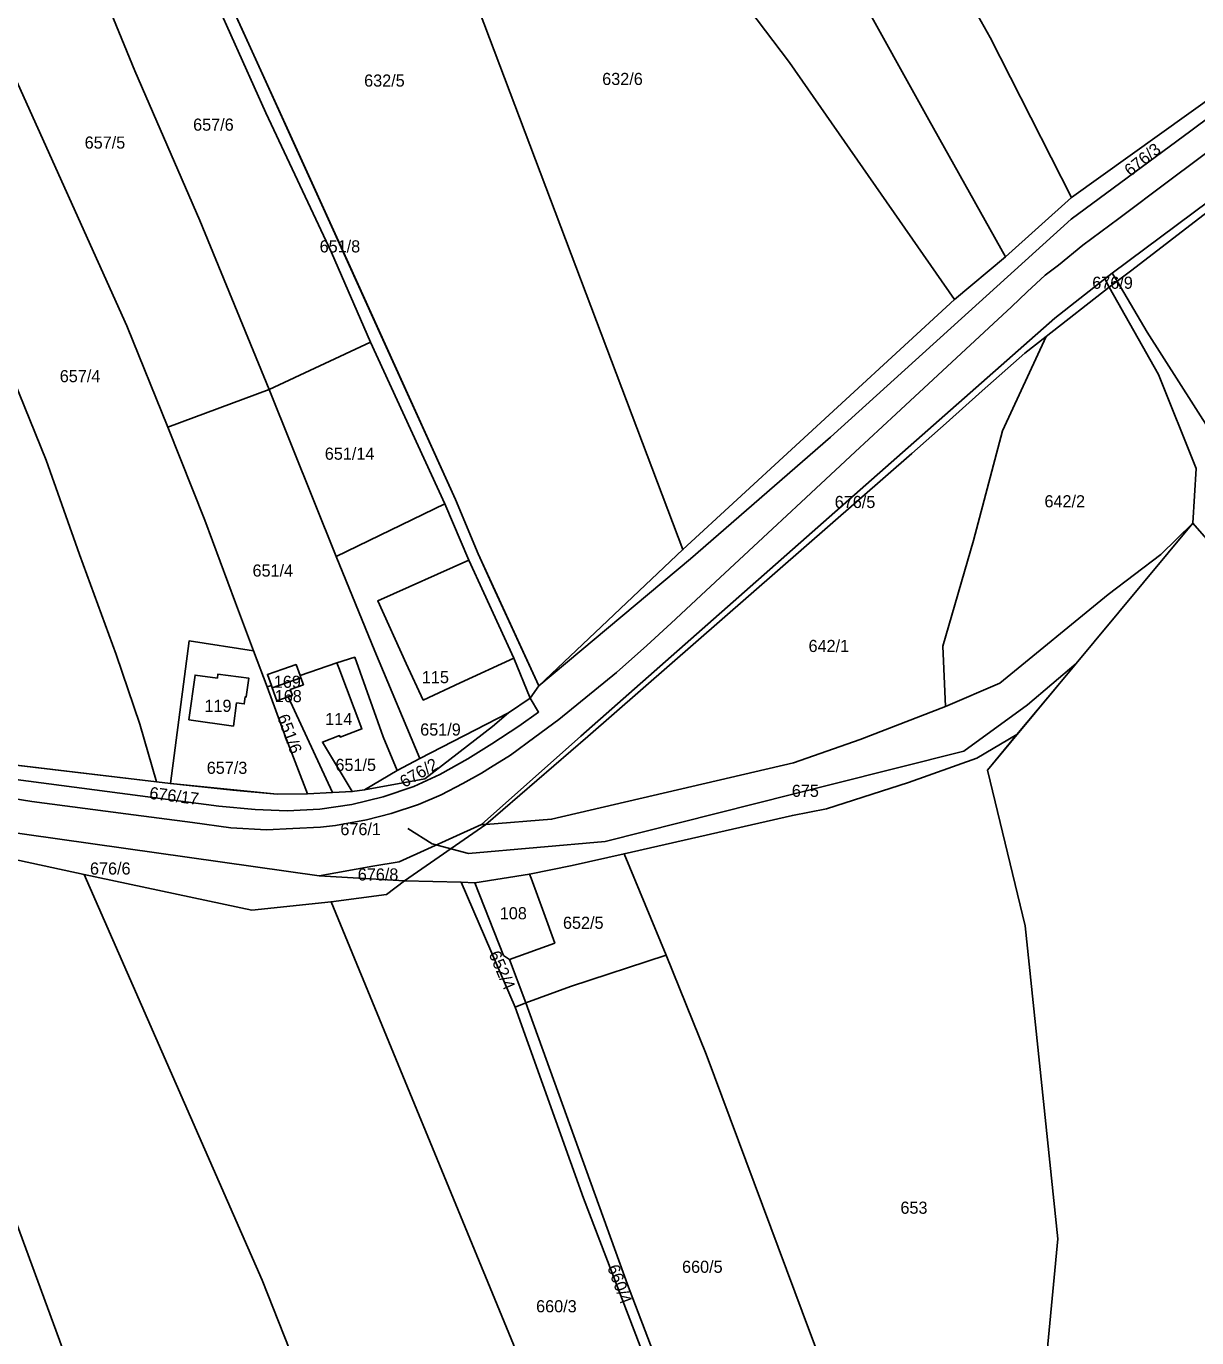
# Model space of a CAD drawing. Extents: x -629983 to -626385, y -1072828 to -1067897.
# Drawn here: x -627472.6 to -627182.9, y -1070989.8 to -1070665.2 of the extents above; entities that cross this region are included whole.
import ezdxf

# ---------------------------------------------------------------- set-up
doc = ezdxf.new("R2010")
doc.units = 0
for name, color, linetype in [('Cesty', 7, 'Continuous'), ('Parcela nároku', 7, 'Continuous'), ('Parcelní číslo', 7, 'Continuous'), ('Plocha PÚ', 7, 'Continuous'), ('Převzatý obvod_Vraclav', 7, 'Continuous'), ('Silnice ŘSD', 7, 'Continuous'), ('Vnitřní obvod_šetřený', 7, 'Continuous')]:
    doc.layers.add(name, color=color, linetype=linetype)

msp = doc.modelspace()

# ---------------------------------------------------------------- linework, layer by layer
at = {"layer": 'Cesty'}
msp.add_lwpolyline([(-627212.76, -1070822.88), (-627224.8, -1070833.14), (-627240.53, -1070844.57), (-627273.7, -1070852.92), (-627329.35, -1070866.93), (-627363.11, -1070869.9), (-627372.12, -1070867.54), (-627378.18, -1070863.7)], dxfattribs=at)
at = {"layer": 'Parcela nároku'}
for points in [[(-627345.75, -1070479.75), (-627344.14, -1070479.15), (-627339.84, -1070477.13), (-627333.5, -1070479.48), (-627296.66, -1070498.52), (-627275.1, -1070508.7), (-627258, -1070516.22), (-627228.28, -1070532.83), (-627198.25, -1070547.66), (-627164.03, -1070550.6), (-627101.84, -1070557.31), (-627079.28, -1070557.75), (-627047.73, -1070561.25), (-627009.17, -1070562.89), (-627133.47, -1070649.92), (-627213.86, -1070707.57), (-627234.07, -1070668.02), (-627251.08, -1070637.59), (-627269.7, -1070609.62), (-627295.58, -1070573.7), (-627307.19, -1070559.96), (-627314.16, -1070551.29), (-627330.36, -1070531.39), (-627360.17, -1070494.95)], [(-627314.16, -1070551.29), (-627330.36, -1070531.39), (-627360.17, -1070494.95), (-627373.54, -1070509.05), (-627353.57, -1070535.93), (-627302.15, -1070602.21), (-627283, -1070629.7), (-627267.06, -1070656.21), (-627249.24, -1070688.39), (-627230.23, -1070722.24), (-627213.86, -1070707.57), (-627234.07, -1070668.02), (-627251.08, -1070637.59), (-627269.7, -1070609.62), (-627295.58, -1070573.7), (-627307.19, -1070559.96)], [(-627267.06, -1070656.21), (-627249.24, -1070688.39), (-627230.23, -1070722.24), (-627242.86, -1070732.84), (-627283.73, -1070674.15), (-627293.78, -1070660.89), (-627306.22, -1070642.08), (-627338.73, -1070596.09), (-627370.14, -1070560.09), (-627392.8, -1070532.82), (-627373.54, -1070509.05), (-627353.57, -1070535.93), (-627302.15, -1070602.21), (-627283, -1070629.7)], [(-627345.73, -1070828.4), (-627310.09, -1070794.7), (-627242.86, -1070732.84), (-627230.23, -1070722.24), (-627213.86, -1070707.57), (-627133.47, -1070649.92), (-627009.17, -1070562.89), (-626993.73, -1070553.31), (-626992.54, -1070553.28), (-627154.49, -1070668.8), (-627184.39, -1070691.07), (-627213.95, -1070712.95), (-627273.55, -1070766.93), (-627308.24, -1070796.99)], [(-627398.36, -1070567.15), (-627370.14, -1070560.09), (-627338.73, -1070596.09), (-627306.22, -1070642.08), (-627293.78, -1070660.89), (-627283.73, -1070674.15), (-627242.86, -1070732.84), (-627310.09, -1070794.7), (-627360.53, -1070661.36)], [(-627360.53, -1070661.36), (-627310.09, -1070794.7), (-627345.73, -1070828.4), (-627360.76, -1070795.75), (-627366.36, -1070782.3), (-627384.74, -1070741.85), (-627400.99, -1070705.92), (-627417.12, -1070670.56), (-627430.56, -1070640.91), (-627435.89, -1070628.45), (-627445.75, -1070607.53), (-627463.29, -1070576.43), (-627398.36, -1070567.15)], [(-627413.29, -1070686.67), (-627433.51, -1070641.56), (-627449.08, -1070608.65), (-627469.47, -1070618.25), (-627445.72, -1070676.24), (-627429.68, -1070713.29), (-627412.5, -1070755.1), (-627387.43, -1070743.37), (-627397.03, -1070721.21)], [(-627430.56, -1070640.91), (-627435.89, -1070628.45), (-627445.75, -1070607.53), (-627449.08, -1070608.65), (-627433.51, -1070641.56), (-627413.29, -1070686.67), (-627397.03, -1070721.21), (-627387.43, -1070743.37), (-627368.97, -1070783.41), (-627363.03, -1070797.32), (-627351.95, -1070821.55), (-627347.85, -1070831.5), (-627345.73, -1070828.4), (-627360.76, -1070795.75), (-627366.36, -1070782.3), (-627384.74, -1070741.85), (-627400.99, -1070705.92), (-627417.12, -1070670.56)], [(-627445.72, -1070676.24), (-627429.68, -1070713.29), (-627412.5, -1070755.1), (-627437.6, -1070764.46), (-627447.75, -1070739.38), (-627476.84, -1070674.65), (-627497.28, -1070630.97), (-627469.47, -1070618.25)], [(-627428.4, -1070787.43), (-627420.85, -1070807.85), (-627416.32, -1070819.79), (-627432.25, -1070817.28), (-627436.93, -1070852.6), (-627440.33, -1070852.16), (-627444.51, -1070837.95), (-627450.33, -1070820.66), (-627459.42, -1070795.95), (-627467.69, -1070772.62), (-627485.16, -1070729.61), (-627494.54, -1070708.53), (-627524.44, -1070643.36), (-627497.28, -1070630.97), (-627476.84, -1070674.65), (-627447.75, -1070739.38), (-627437.6, -1070764.46)], [(-627135.92, -1070675.75), (-627203.84, -1070726.3), (-627202.58, -1070728.32), (-627198.97, -1070725.59), (-627161.65, -1070696.9), (-627086.98, -1070641.42), (-627087.58, -1070639.08)], [(-627526.57, -1070644.43), (-627524.44, -1070643.36), (-627494.54, -1070708.53), (-627485.16, -1070729.61), (-627467.69, -1070772.62), (-627459.42, -1070795.95), (-627450.33, -1070820.66), (-627444.51, -1070837.95), (-627440.33, -1070852.16), (-627482.19, -1070847.21), (-627487.27, -1070833.79), (-627496.33, -1070806.96), (-627518.25, -1070750.64), (-627541.19, -1070696.77), (-627538.48, -1070690.73)], [(-627359.96, -1070862.72), (-627335.31, -1070840.92), (-627218.06, -1070737.43), (-627205.69, -1070727.72), (-627204.61, -1070729.74), (-627220.17, -1070742.01), (-627225.42, -1070746.14), (-627236.01, -1070755.45), (-627244.91, -1070763.47), (-627253.44, -1070770.95), (-627333.6, -1070840.96), (-627358.84, -1070862.72)], [(-627205.69, -1070727.72), (-627203.84, -1070726.3), (-627202.58, -1070728.32), (-627204.61, -1070729.74)], [(-627124.68, -1070815.56), (-627100.86, -1070825.79), (-627112.72, -1070834.32), (-627114.07, -1070833.53), (-627155.58, -1070814.85), (-627170.74, -1070803.18), (-627183.85, -1070788.14), (-627183.07, -1070774.61), (-627192.4, -1070751.35), (-627204.61, -1070729.74), (-627202.58, -1070728.32), (-627195.15, -1070740.89), (-627179.46, -1070765.48), (-627171.13, -1070779.58), (-627160.79, -1070795.62), (-627147.68, -1070806.17)], [(-627220.17, -1070742.01), (-627204.61, -1070729.74), (-627192.4, -1070751.35), (-627183.07, -1070774.61), (-627183.85, -1070788.14), (-627191.81, -1070795.9), (-627204.83, -1070805.81), (-627231.68, -1070827.78), (-627245.05, -1070833.52), (-627245.75, -1070818.59), (-627238.15, -1070792.48), (-627231.02, -1070765.37)], [(-627387.43, -1070743.37), (-627368.97, -1070783.41), (-627395.86, -1070796.42), (-627412.5, -1070755.1)], [(-627220.17, -1070742.01), (-627231.02, -1070765.37), (-627238.15, -1070792.48), (-627245.75, -1070818.59), (-627245.05, -1070833.52), (-627266.24, -1070841.69), (-627282.74, -1070847.49), (-627342.58, -1070861.45), (-627358.84, -1070862.72), (-627333.6, -1070840.96), (-627253.44, -1070770.95), (-627244.91, -1070763.47), (-627236.01, -1070755.45), (-627225.42, -1070746.14)], [(-627411.94, -1070828.31), (-627412.92, -1070825.6), (-627409.06, -1070824.28), (-627405.8, -1070823.17), (-627404.82, -1070825.87), (-627395.71, -1070822.75), (-627391.28, -1070821.34), (-627384.3, -1070841.06), (-627380.78, -1070849.34), (-627375.19, -1070846.37), (-627386.3, -1070819.87), (-627395.86, -1070796.42), (-627412.5, -1070755.1), (-627437.6, -1070764.46), (-627428.4, -1070787.43), (-627420.85, -1070807.85), (-627416.32, -1070819.79), (-627412.96, -1070828.66)], [(-627378.56, -1070822.89), (-627385.61, -1070807.42), (-627363.03, -1070797.32), (-627368.97, -1070783.41), (-627395.86, -1070796.42), (-627386.3, -1070819.87), (-627375.19, -1070846.37), (-627353.23, -1070835.08), (-627347.85, -1070831.5), (-627351.95, -1070821.55), (-627365.18, -1070827.7), (-627374.34, -1070831.96)], [(-627217.22, -1070828.24), (-627208.31, -1070817.53), (-627183.85, -1070788.14), (-627191.81, -1070795.9), (-627204.83, -1070805.81), (-627231.68, -1070827.78), (-627245.05, -1070833.52), (-627266.24, -1070841.69), (-627282.74, -1070847.49), (-627342.58, -1070861.45), (-627358.84, -1070862.72), (-627378.98, -1070876.68), (-627364.95, -1070877.04), (-627361.61, -1070877.18), (-627348.05, -1070875.02), (-627337.52, -1070872.91), (-627324.65, -1070869.98), (-627282.97, -1070860.49), (-627274.55, -1070858.83), (-627254.24, -1070852.32), (-627237.3, -1070846.31), (-627227.43, -1070840.51)], [(-627363.03, -1070797.32), (-627351.95, -1070821.55), (-627365.18, -1070827.7), (-627374.34, -1070831.96), (-627378.56, -1070822.89), (-627385.61, -1070807.42)], [(-627408.71, -1070840.35), (-627402.98, -1070855.15), (-627410.49, -1070855.25), (-627421.44, -1070854.21), (-627436.93, -1070852.6), (-627432.25, -1070817.28), (-627416.32, -1070819.79), (-627412.96, -1070828.66)], [(-627395.23, -1070823.98), (-627389.52, -1070839.07), (-627394.9, -1070841.11), (-627395.06, -1070840.76), (-627399.32, -1070842.35), (-627391.9, -1070854.61), (-627396.81, -1070854.85), (-627407.8, -1070831.18), (-627406.72, -1070830.81), (-627407.26, -1070829.3), (-627403.99, -1070828.15), (-627404.62, -1070826.41), (-627404.82, -1070825.87), (-627395.71, -1070822.75)], [(-627384.3, -1070841.06), (-627391.28, -1070821.34), (-627395.71, -1070822.75), (-627395.23, -1070823.98), (-627389.52, -1070839.07), (-627394.9, -1070841.11), (-627395.06, -1070840.76), (-627399.32, -1070842.35), (-627391.9, -1070854.61), (-627388.87, -1070854.16), (-627380.78, -1070849.34)], [(-627425.15, -1070825.51), (-627425.28, -1070826.52), (-627430.81, -1070825.75), (-627432.34, -1070836.81), (-627421.34, -1070838.38), (-627420.55, -1070832.65), (-627418.64, -1070832.91), (-627418.4, -1070831.15), (-627418.14, -1070831.19), (-627417.51, -1070826.57)], [(-627420.55, -1070832.65), (-627418.64, -1070832.91), (-627418.4, -1070831.15), (-627418.14, -1070831.19), (-627417.51, -1070826.57), (-627425.15, -1070825.51), (-627425.28, -1070826.52), (-627430.81, -1070825.75), (-627432.34, -1070836.81), (-627421.34, -1070838.38)], [(-627412.92, -1070825.6), (-627409.06, -1070824.28), (-627405.8, -1070823.17), (-627404.82, -1070825.87), (-627404.62, -1070826.41), (-627411.72, -1070828.91), (-627411.94, -1070828.31)], [(-627410.55, -1070832.11), (-627411.72, -1070828.91), (-627411.94, -1070828.31), (-627412.96, -1070828.66), (-627408.71, -1070840.35), (-627402.98, -1070855.15), (-627396.81, -1070854.85), (-627407.8, -1070831.18)], [(-627407.26, -1070829.3), (-627406.72, -1070830.81), (-627407.8, -1070831.18), (-627410.55, -1070832.11), (-627411.72, -1070828.91), (-627404.62, -1070826.41), (-627403.99, -1070828.15)], [(-627388.87, -1070854.16), (-627380.78, -1070849.34), (-627375.19, -1070846.37), (-627353.23, -1070835.08), (-627357.2, -1070838.49), (-627373.98, -1070851.44)], [(-627324.65, -1070869.98), (-627282.97, -1070860.49), (-627274.55, -1070858.83), (-627254.24, -1070852.32), (-627237.3, -1070846.31), (-627227.43, -1070840.51), (-627234.72, -1070849.27), (-627225.38, -1070887.83), (-627217.27, -1070965.31), (-627222.05, -1071015.66), (-627216.92, -1071077.12), (-627218.51, -1071078), (-627242.92, -1071082.98), (-627278.49, -1070988.8), (-627304.36, -1070919.55), (-627314.21, -1070895.06)], [(-627425.39, -1071101.61), (-627464.39, -1070990.31), (-627494.83, -1070907.68), (-627511.34, -1070863.62), (-627558.97, -1070852.76), (-627563.32, -1070867.25), (-627565.13, -1070881.01), (-627553.22, -1070912.19), (-627487.28, -1071091.1), (-627484.82, -1071098.49), (-627477.62, -1071120.08), (-627464.68, -1071117.19), (-627425.29, -1071264.47), (-627411.23, -1071265.41), (-627404.64, -1071260.81), (-627372.04, -1071256.74)], [(-627400.11, -1070875.43), (-627378.98, -1070876.68), (-627383.46, -1070880.08), (-627397.15, -1070881.84), (-627416.76, -1070883.94), (-627458.27, -1070875.13), (-627511.34, -1070863.62), (-627512.8, -1070859.53)], [(-627511.34, -1070863.62), (-627458.27, -1070875.13), (-627414.24, -1070975.53), (-627351.5, -1071134.14), (-627344.19, -1071153.05), (-627310.58, -1071241.74), (-627330.46, -1071244.09), (-627344.95, -1071240.94), (-627370.43, -1071256.59), (-627372.04, -1071256.74), (-627425.39, -1071101.61), (-627464.39, -1070990.31), (-627494.83, -1070907.68)], [(-627386.84, -1070873.07), (-627380.27, -1070871.95), (-627359.96, -1070862.72), (-627358.84, -1070862.72), (-627378.98, -1070876.68), (-627400.11, -1070875.43)], [(-627314.21, -1070895.06), (-627324.65, -1070869.98), (-627337.52, -1070872.91), (-627348.05, -1070875.02), (-627347.65, -1070876.03), (-627344.53, -1070884.58), (-627341.79, -1070892.1), (-627353, -1070896.16), (-627348.99, -1070906.83), (-627337.88, -1070902.81)], [(-627243.27, -1071225.13), (-627253.31, -1071197.18), (-627293.78, -1071090.43), (-627315.1, -1071093.36), (-627352.03, -1070991.41), (-627397.15, -1070881.84), (-627416.76, -1070883.94), (-627458.27, -1070875.13), (-627414.24, -1070975.53), (-627351.5, -1071134.14), (-627344.19, -1071153.05), (-627310.58, -1071241.74), (-627279.45, -1071238.38), (-627256.78, -1071225.7)], [(-627334.65, -1070955.19), (-627351.59, -1070907.93), (-627364.95, -1070877.04), (-627378.98, -1070876.68), (-627383.46, -1070880.08), (-627397.15, -1070881.84), (-627352.03, -1070991.41), (-627315.1, -1071093.36), (-627293.78, -1071090.43), (-627283.43, -1071089)], [(-627364.95, -1070877.04), (-627361.61, -1070877.18), (-627354.49, -1070895.13), (-627353, -1070896.16), (-627348.99, -1070906.83), (-627351.59, -1070907.93)], [(-627344.53, -1070884.58), (-627347.65, -1070876.03), (-627348.05, -1070875.02), (-627361.61, -1070877.18), (-627354.49, -1070895.13), (-627353, -1070896.16), (-627341.79, -1070892.1)], [(-627314.21, -1070895.06), (-627304.36, -1070919.55), (-627278.49, -1070988.8), (-627242.92, -1071082.98), (-627249.56, -1071084.34), (-627281.03, -1071088.67), (-627323.76, -1070976.6), (-627348.99, -1070906.83), (-627337.88, -1070902.81)], [(-627348.99, -1070906.83), (-627323.76, -1070976.6), (-627281.03, -1071088.67), (-627283.43, -1071089), (-627334.65, -1070955.19), (-627351.59, -1070907.93)]]:
    msp.add_lwpolyline(points, close=True, dxfattribs=at)
for points in [[(-627483.4, -1070850.5), (-627424.93, -1070858.24), (-627415.96, -1070859.06), (-627407.99, -1070859.33), (-627399.98, -1070858.97), (-627392.06, -1070857.81), (-627384.28, -1070855.87), (-627376.68, -1070853.37), (-627370.28, -1070850.4), (-627363.31, -1070846.47), (-627357.37, -1070842.79), (-627350.7, -1070838.37), (-627345.8, -1070834.94), (-627347.85, -1070831.5), (-627345.73, -1070828.4), (-627308.24, -1070796.99), (-627273.55, -1070766.93), (-627213.95, -1070712.95), (-627184.39, -1070691.07), (-627154.49, -1070668.8), (-626992.54, -1070553.28)], [(-627087.58, -1070639.08), (-627135.92, -1070675.75), (-627203.84, -1070726.3), (-627205.69, -1070727.72), (-627218.06, -1070737.43), (-627335.31, -1070840.92), (-627359.96, -1070862.72), (-627380.27, -1070871.95), (-627386.84, -1070873.07), (-627400.11, -1070875.43), (-627512.8, -1070859.53)], [(-627161.65, -1070696.9), (-627198.97, -1070725.59), (-627202.58, -1070728.32), (-627195.15, -1070740.89), (-627179.46, -1070765.48)], [(-627482.19, -1070847.21), (-627440.33, -1070852.16), (-627436.93, -1070852.6), (-627421.44, -1070854.21), (-627410.49, -1070855.25), (-627402.98, -1070855.15), (-627396.81, -1070854.85), (-627391.9, -1070854.61), (-627388.87, -1070854.16), (-627373.98, -1070851.44), (-627357.2, -1070838.49), (-627353.23, -1070835.08), (-627347.85, -1070831.5), (-627345.8, -1070834.94), (-627350.7, -1070838.37), (-627357.37, -1070842.79), (-627363.31, -1070846.47), (-627370.28, -1070850.4), (-627376.68, -1070853.37), (-627384.28, -1070855.87), (-627392.06, -1070857.81), (-627399.98, -1070858.97), (-627407.99, -1070859.33), (-627415.96, -1070859.06), (-627424.93, -1070858.24), (-627483.4, -1070850.5)]]:
    msp.add_lwpolyline(points, dxfattribs=at)
at = {"layer": 'Plocha PÚ'}
for points in [[(-627430.56, -1070640.91), (-627417.12, -1070670.56), (-627407.65, -1070691.38), (-627392.86, -1070723.88), (-627366.36, -1070782.3), (-627360.76, -1070795.75), (-627357, -1070803.92), (-627345.73, -1070828.4), (-627347.85, -1070831.5), (-627353.23, -1070835.08), (-627375.19, -1070846.37), (-627380.78, -1070849.34), (-627388.87, -1070854.16), (-627391.9, -1070854.61), (-627396.81, -1070854.85), (-627402.98, -1070855.15), (-627410.49, -1070855.25), (-627436.93, -1070852.6), (-627440.33, -1070852.16)], [(-627222.05, -1071015.66), (-627217.27, -1070965.31), (-627225.38, -1070887.83), (-627234.72, -1070849.27), (-627227.43, -1070840.51), (-627217.22, -1070828.24), (-627208.31, -1070817.53), (-627183.85, -1070788.14), (-627170.74, -1070803.18), (-627155.58, -1070814.85), (-627114.07, -1070833.53), (-627112.72, -1070834.32), (-627076.34, -1070855.66), (-627044.98, -1070882.21), (-627037.53, -1070897.08), (-627032.6, -1070896.33), (-627025.74, -1070895.3), (-627008.7, -1070900.39), (-626983.91, -1070896.06), (-626968.21, -1070856.09), (-626954.89, -1070842.05), (-626929.36, -1070835.69), (-626900.86, -1070813.99), (-626870.88, -1070806.24)], [(-627440.33, -1070852.16), (-627482.19, -1070847.21)]]:
    msp.add_lwpolyline(points, dxfattribs=at)
msp.add_lwpolyline([(-627324.65, -1070869.98), (-627314.21, -1070895.06), (-627337.88, -1070902.81), (-627348.99, -1070906.83), (-627353, -1070896.16), (-627354.49, -1070895.13), (-627361.61, -1070877.18), (-627348.05, -1070875.02), (-627337.52, -1070872.91)], close=True, dxfattribs=at)
at = {"layer": 'Převzatý obvod_Vraclav'}
msp.add_lwpolyline([(-626870.88, -1070806.24), (-626900.86, -1070813.99), (-626929.36, -1070835.69), (-626954.89, -1070842.05), (-626968.21, -1070856.09), (-626983.91, -1070896.06), (-627008.7, -1070900.39), (-627025.74, -1070895.3), (-627032.6, -1070896.33), (-627037.53, -1070897.08), (-627044.98, -1070882.21), (-627076.34, -1070855.66), (-627114.07, -1070833.53), (-627155.58, -1070814.85), (-627170.74, -1070803.18), (-627183.85, -1070788.14), (-627208.31, -1070817.53), (-627217.22, -1070828.24), (-627234.72, -1070849.27), (-627225.38, -1070887.83), (-627217.27, -1070965.31), (-627222.05, -1071015.66)], dxfattribs=at)
at = {"layer": 'Silnice ŘSD'}
for p, q in [((-627189.91, -1070703.55), (-627162.86, -1070683.28)), ((-627202.19, -1070712.75), (-627189.91, -1070703.55)), ((-627211.09, -1070719.42), (-627202.19, -1070712.75)), ((-627217.12, -1070724.37), (-627211.09, -1070719.42)), ((-627220.4, -1070726.8), (-627217.12, -1070724.37)), ((-627224.85, -1070730.94), (-627220.4, -1070726.8)), ((-627228.79, -1070734.61), (-627224.85, -1070730.94)), ((-627233.22, -1070738.73), (-627228.79, -1070734.61)), ((-627257.27, -1070761.1), (-627233.22, -1070738.73)), ((-627267.44, -1070770.56), (-627257.27, -1070761.1)), ((-627280.79, -1070782.97), (-627267.44, -1070770.56)), ((-627287.9, -1070789.58), (-627280.79, -1070782.97)), ((-627304.39, -1070804.9), (-627287.9, -1070789.58)), ((-627313, -1070812.9), (-627304.39, -1070804.9)), ((-627318.98, -1070818.46), (-627313, -1070812.9)), ((-627326.51, -1070825.12), (-627318.98, -1070818.46)), ((-627340.76, -1070836.73), (-627326.51, -1070825.12)), ((-627346.75, -1070841.15), (-627340.76, -1070836.73)), ((-627352.74, -1070845.57), (-627346.75, -1070841.15)), ((-627357.74, -1070848.67), (-627352.74, -1070845.57)), ((-627359.9, -1070850.01), (-627357.74, -1070848.67)), ((-627503.72, -1070851.92), (-627471.23, -1070857.06)), ((-627364.57, -1070852.61), (-627359.9, -1070850.01)), ((-627375.49, -1070857.8), (-627369.94, -1070855.4)), ((-627369.94, -1070855.4), (-627364.57, -1070852.61)), ((-627471.23, -1070857.06), (-627447.98, -1070860.11)), ((-627382.29, -1070860), (-627375.49, -1070857.8)), ((-627447.98, -1070860.11), (-627431.45, -1070862.28)), ((-627396.09, -1070862.98), (-627388.39, -1070861.61)), ((-627388.39, -1070861.61), (-627382.29, -1070860)), ((-627431.45, -1070862.28), (-627421.95, -1070863.53)), ((-627421.95, -1070863.53), (-627413.12, -1070864.03)), ((-627413.12, -1070864.03), (-627406.59, -1070863.73)), ((-627406.59, -1070863.73), (-627399.8, -1070863.42)), ((-627399.8, -1070863.42), (-627396.09, -1070862.98))]:
    msp.add_line(p, q, dxfattribs=at)
at = {"layer": 'Vnitřní obvod_šetřený'}
for p, q in [((-627430.56, -1070640.91), (-627417.12, -1070670.56)), ((-627417.12, -1070670.56), (-627400.26, -1070707.63)), ((-627400.26, -1070707.63), (-627366.36, -1070782.3)), ((-627366.36, -1070782.3), (-627360.76, -1070795.75)), ((-627360.76, -1070795.75), (-627345.73, -1070828.4)), ((-627345.73, -1070828.4), (-627347.85, -1070831.5)), ((-627347.85, -1070831.5), (-627353.23, -1070835.08)), ((-627353.23, -1070835.08), (-627375.19, -1070846.37)), ((-627440.33, -1070852.16), (-627482.19, -1070847.21)), ((-627375.19, -1070846.37), (-627380.78, -1070849.34)), ((-627436.93, -1070852.6), (-627440.33, -1070852.16)), ((-627380.78, -1070849.34), (-627388.87, -1070854.16)), ((-627410.49, -1070855.25), (-627436.93, -1070852.6)), ((-627402.98, -1070855.15), (-627410.49, -1070855.25)), ((-627396.81, -1070854.85), (-627402.98, -1070855.15)), ((-627391.9, -1070854.61), (-627396.81, -1070854.85)), ((-627388.87, -1070854.16), (-627391.9, -1070854.61)), ((-627337.52, -1070872.91), (-627324.65, -1070869.98)), ((-627324.65, -1070869.98), (-627314.21, -1070895.06)), ((-627348.05, -1070875.02), (-627337.52, -1070872.91)), ((-627361.61, -1070877.18), (-627348.05, -1070875.02)), ((-627354.49, -1070895.13), (-627361.61, -1070877.18)), ((-627353, -1070896.16), (-627354.49, -1070895.13)), ((-627348.99, -1070906.83), (-627353, -1070896.16)), ((-627314.21, -1070895.06), (-627337.88, -1070902.81)), ((-627337.88, -1070902.81), (-627348.99, -1070906.83))]:
    msp.add_line(p, q, dxfattribs=at)

# ---------------------------------------------------------------- texts
at = {"layer": 'Parcelní číslo'}
for s, p in [('632/6', (-627330.05, -1070679.75)), ('632/5', (-627388.97, -1070680.15)), ('657/6', (-627431.3, -1070691.06)), ('657/5', (-627458.15, -1070695.5)), ('651/8', (-627399.99, -1070721.18)), ('676/9', (-627208.76, -1070730.18)), ('657/4', (-627464.31, -1070753.29)), ('651/14', (-627398.71, -1070772.48)), ('676/5', (-627272.5, -1070784.43)), ('642/2', (-627220.59, -1070784.26)), ('651/4', (-627416.6, -1070801.4)), ('642/1', (-627278.98, -1070820.06)), ('169', (-627411.33, -1070828.92)), ('115', (-627374.68, -1070827.77)), ('168', (-627411.11, -1070832.47)), ('119', (-627428.49, -1070834.87)), ('114', (-627398.6, -1070838.14)), ('651/9', (-627375.1, -1070840.74)), ('657/3', (-627427.93, -1070850.21)), ('651/5', (-627396.08, -1070849.49)), ('675', (-627283.12, -1070855.9)), ('676/1', (-627394.86, -1070865.38)), ('676/6', (-627456.83, -1070875.13)), ('676/8', (-627390.55, -1070876.61)), ('108', (-627355.4, -1070886.2)), ('652/5', (-627339.76, -1070888.56)), ('653', (-627256.24, -1070959.06)), ('660/5', (-627310.29, -1070973.68)), ('660/3', (-627346.41, -1070983.45))]:
    msp.add_text(s, height=3, dxfattribs=at).set_placement(p)
for s, rotation, p in [('676/3', 38.8162, (-627199.32, -1070702.5)), ('651/6', 290.3045, (-627410.56, -1070836.1)), ('676/2', 29.9889, (-627379.03, -1070853.74)), ('676/17', 352.8, (-627442.26, -1070856.37)), ('652/4', 293.4201, (-627358.22, -1070894.79)), ('660/4', 290.2657, (-627328.85, -1070972.29))]:
    msp.add_text(s, height=3, rotation=rotation, dxfattribs=at).set_placement(p)

doc.saveas('drawing.dxf')
